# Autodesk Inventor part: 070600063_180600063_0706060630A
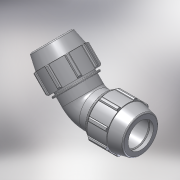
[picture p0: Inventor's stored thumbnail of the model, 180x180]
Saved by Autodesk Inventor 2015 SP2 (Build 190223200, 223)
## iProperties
Created: 2017-02
Part Number: 070600063_180600063_0706060630A
Material: PVC-Piping
Description: PLASSON 45° ELBOW 63-63
Document SubType Name: Modeling
Designer: KIM
Mass: 92.6774 g
Surface Area: 199.44 cm^2
Volume: 66.1981 cm^3
Density: 1.4 g/cm^3
Appearance: Smooth - White
Author: KIM
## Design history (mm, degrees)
derived "07060.ipt"
feature "Solid1::07060.ipt"
tag "TaggingFeature1"
body "Solid1"
other parameters: "d2" = 63, "d4" = 10.83333, "d5" = 32.5, "d7" = 113, "d9" = 18.57143, "d11" = 4.33333, "d13" = 120 deg, "d14" = 88.2, "d15" = 12 deg, "d16" = 98.31, "d18" = 3.15, "d19" = 35 deg, "d20" = 17.5 deg, "d21" = 105.09, "d23" = 0, "d25" = 360 deg, "d27" = 2.26, "d33" = 1.26, "d42" = 48.1, "d43" = 3.39, "d46" = 1.89, "d59" = 135 deg, "d67" = 84.75, "d68" = 4.33333, "d72" = 1.5, "d73" = 0, "d74" = 0, "d_" = 63, "E_" = 113
